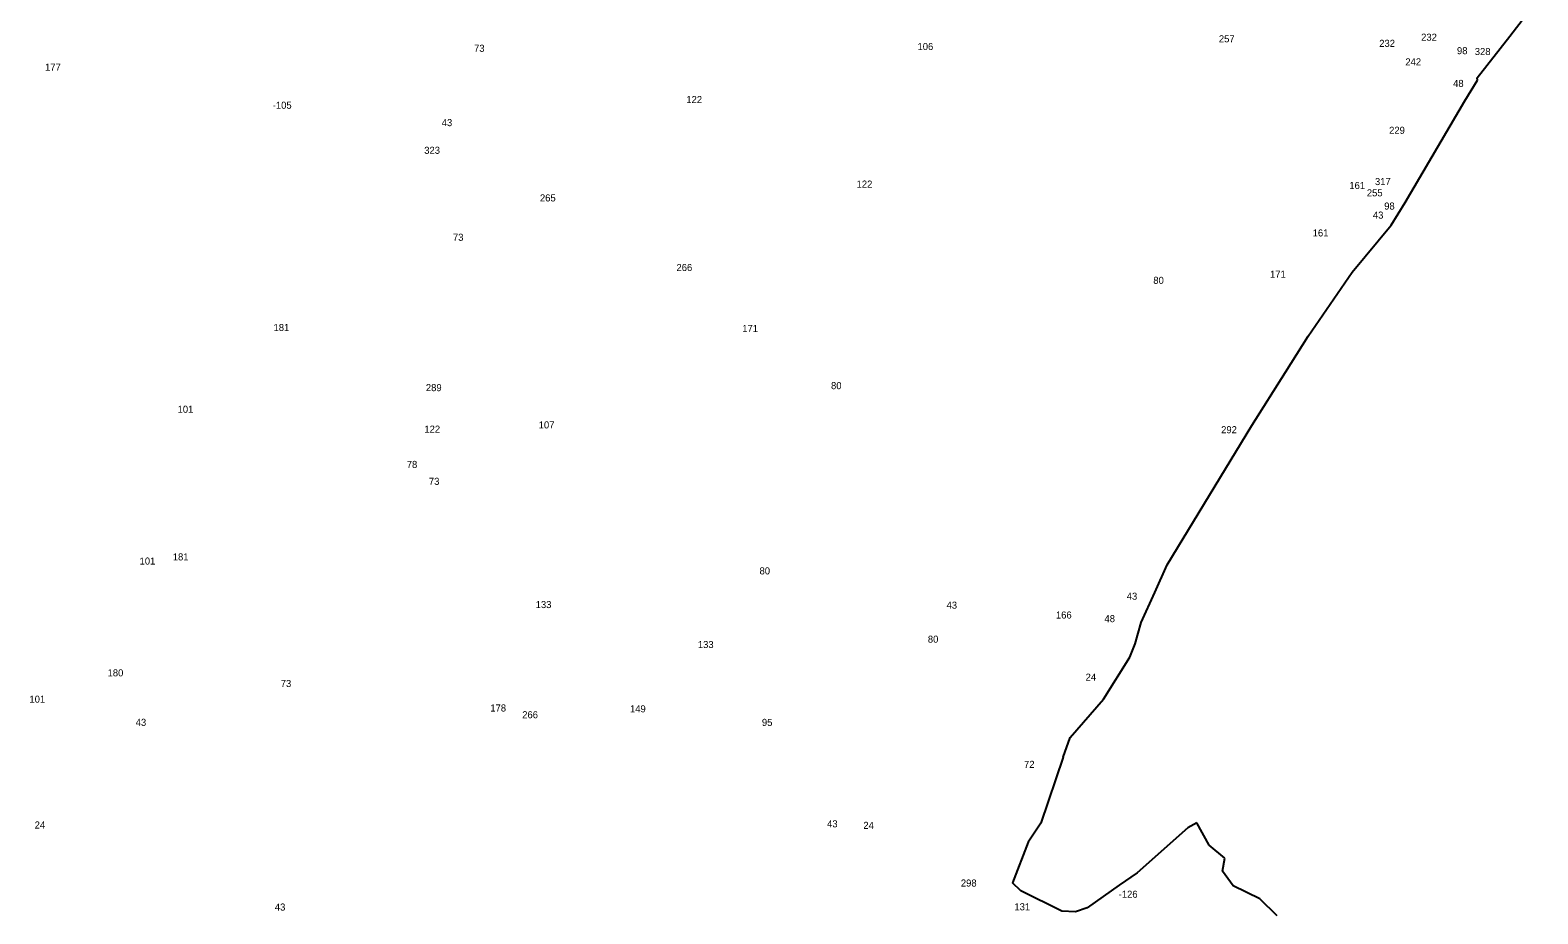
# Model space of a CAD drawing. Extents: x -780116 to -776974, y -980293 to -977147.
# Drawn here: x -778481 to -777128, y -978721 to -977928 of the extents above; entities that cross this region are included whole.
import ezdxf

# ---------------------------------------------------------------- set-up
doc = ezdxf.new("R2010")
doc.units = 0
doc.layers.add('Vrstva 13', color=7, linetype='Continuous')
doc.layers.add('Vrstva 24', color=7, linetype='Continuous')

msp = doc.modelspace()

# ---------------------------------------------------------------- linework, layer by layer
at = {"layer": 'Vrstva 13'}
for p, q in [((-777153.39, -977933.27), (-777128.21, -977900.39)), ((-777182.59, -977970.45), (-777153.39, -977933.27)), ((-777182.3, -977972.64), (-777182.59, -977970.45)), ((-777193.66, -977991.28), (-777182.3, -977972.64)), ((-777247.41, -978082.46), (-777193.66, -977991.28)), ((-777259.85, -978102.83), (-777247.41, -978082.46)), ((-777294.8, -978144.9), (-777259.85, -978102.83)), ((-777334.19, -978202.52), (-777294.8, -978144.9)), ((-777354.54, -978234.59), (-777334.19, -978202.52)), ((-777384.75, -978282.62), (-777354.54, -978234.59)), ((-777460.79, -978407.64), (-777384.75, -978282.62)), ((-777471.89, -978432.42), (-777460.79, -978407.64)), ((-777484.07, -978459.49), (-777471.89, -978432.42)), ((-777489.57, -978478.4), (-777484.07, -978459.49)), ((-777494.24, -978490.62), (-777489.57, -978478.4)), ((-777518.08, -978528.25), (-777494.24, -978490.62)), ((-777547.98, -978562.47), (-777518.08, -978528.25)), ((-777554.28, -978580.32), (-777547.98, -978562.47)), ((-777554.28, -978580.32), (-777574.19, -978639.49)), ((-777574.19, -978639.49), (-777585.44, -978656.6)), ((-777442.23, -978643.54), (-777487.72, -978684.01)), ((-777434.23, -978639.28), (-777442.23, -978643.54)), ((-777423.3, -978659.35), (-777434.23, -978639.28)), ((-777585.44, -978656.6), (-777599.62, -978693.04)), ((-777409.16, -978670.98), (-777423.3, -978659.35)), ((-777411.31, -978682.46), (-777409.16, -978670.98)), ((-777487.72, -978684.01), (-777503.97, -978695.05)), ((-777401.68, -978695.72), (-777411.31, -978682.46)), ((-777592.07, -978700.26), (-777599.62, -978693.04)), ((-777555.24, -978718.41), (-777592.07, -978700.26)), ((-777503.97, -978695.05), (-777532.77, -978715.3)), ((-777377.55, -978707.5), (-777401.68, -978695.72)), ((-777362.22, -978722.53), (-777377.55, -978707.5)), ((-777543.02, -978719.15), (-777555.24, -978718.41)), ((-777532.77, -978715.3), (-777543.02, -978719.15))]:
    msp.add_line(p, q, dxfattribs=at)

# ---------------------------------------------------------------- texts
at = {"layer": 'Vrstva 24'}
for s, p in [('73', (-778082.819, -977947.224)), ('106', (-777684.876, -977945.684)), ('257', (-777414.448, -977938.714)), ('232', (-777270.553, -977942.814)), ('232', (-777232.943, -977937.284)), ('98', (-777200.785, -977949.384)), ('328', (-777184.803, -977950.164)), ('242', (-777247.113, -977959.404)), ('177', (-778467.78, -977964.194)), ('48', (-777204.245, -977978.774)), ('-105', (-778263.439, -977998.354)), ('122', (-777892.341, -977993.244)), ('43', (-778111.815, -978013.954)), ('229', (-777261.673, -978020.834)), ('323', (-778127.513, -978038.784)), ('122', (-777739.531, -978069.104)), ('161', (-777297.389, -978070.354)), ('317', (-777274.376, -978066.844)), ('265', (-778023.683, -978081.524)), ('255', (-777281.663, -978076.964)), ('43', (-777276.235, -978096.934)), ('98', (-777266.095, -978088.824)), ('73', (-778101.759, -978116.824)), ('161', (-777330.269, -978112.954)), ('266', (-777901.163, -978143.954)), ('171', (-777368.563, -978150.024)), ('80', (-777473.27, -978155.494)), ('181', (-778262.769, -978197.774)), ('171', (-777842.123, -978198.674)), ('289', (-778126.043, -978251.774)), ('80', (-777762.47, -978249.984)), ('101', (-778348.833, -978271.174)), ('107', (-778024.811, -978285.234)), ('122', (-778127.381, -978289.014)), ('292', (-777412.413, -978289.544)), ('78', (-778143.179, -978320.694)), ('73', (-778123.349, -978335.854)), ('101', (-778382.953, -978407.404)), ('181', (-778353.159, -978403.674)), ('80', (-777826.61, -978416.234)), ('133', (-778027.501, -978446.454)), ('43', (-777658.805, -978447.004)), ('43', (-777497.135, -978438.954)), ('166', (-777560.661, -978455.834)), ('48', (-777517.105, -978459.084)), ('80', (-777675.59, -978477.484)), ('133', (-777881.981, -978482.314)), ('180', (-778411.656, -978507.734)), ('73', (-778256.279, -978517.264)), ('24', (-777534.025, -978511.594)), ('101', (-778481.793, -978531.374)), ('178', (-778068.215, -978539.254)), ('266', (-778039.603, -978545.324)), ('149', (-777942.891, -978540.014)), ('43', (-778386.425, -978552.134)), ('95', (-777824.505, -978552.194)), ('72', (-777589.269, -978589.864)), ('24', (-778477.095, -978644.264)), ('43', (-777766.015, -978643.214)), ('24', (-777733.465, -978644.614)), ('298', (-777645.973, -978696.354)), ('-126', (-777504.365, -978706.414)), ('43', (-778261.555, -978717.894)), ('131', (-777597.929, -978717.674))]:
    msp.add_text(s, height=6.336, dxfattribs=at).set_placement(p)

doc.saveas('drawing.dxf')
